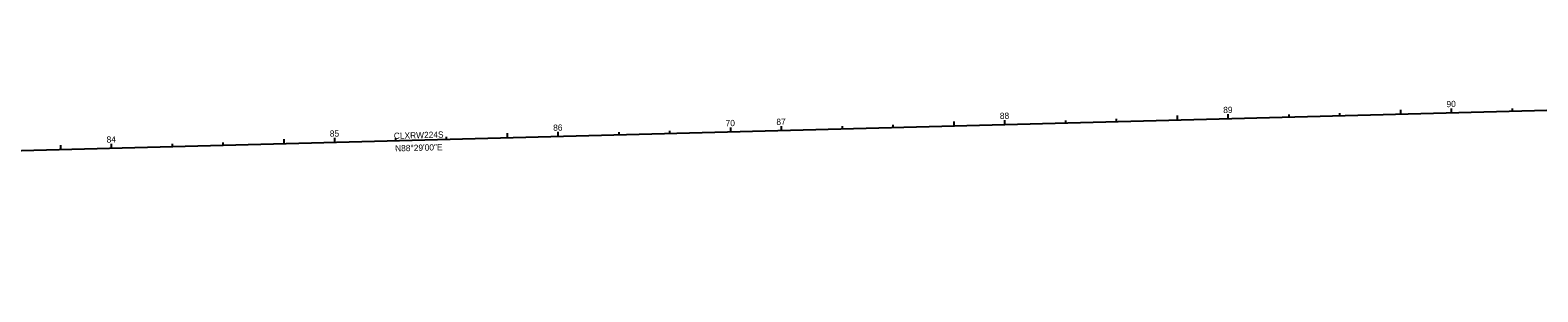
# Model space of a CAD drawing. Extents: x 2402033 to 2407434, y 498266 to 500417.
# Drawn here: x 2405397 to 2406072, y 498666 to 498783 of the extents above; entities that cross this region are included whole.
import ezdxf

# ---------------------------------------------------------------- set-up
doc = ezdxf.new("R2010")
doc.units = 0
for name, color, linetype in [('DR_P_Inlet_Protection', 7, 'Continuous'), ('DR_X_Cells', 7, 'Continuous'), ('DR_X_Elev_Flow', 7, 'Continuous'), ('PV_P_EOP', 7, 'Continuous'), ('PV_P_Shoulder', 7, 'Continuous'), ('RD_P_GR_Lt', 7, 'Continuous'), ('SN_X_Public', 7, 'Continuous'), ('UT_X_Gas_Cells', 7, 'Continuous'), ('UT_X_Telecom_Cells', 7, 'Continuous')]:
    doc.layers.add(name, color=color, linetype=linetype)

msp = doc.modelspace()

# ---------------------------------------------------------------- linework, layer by layer
at = {"layer": 'PV_P_EOP'}
msp.add_line((2403004.47, 498665.82), (2407431.7, 498783.04), dxfattribs=at)
at = {"layer": 'PV_P_Shoulder'}
for p, q in [((2405833.48, 498740.72), (2405833.45, 498741.92)), ((2405910.7, 498742.77), (2405910.67, 498743.96)), ((2405933.45, 498743.37), (2405933.41, 498744.57)), ((2406010.67, 498745.41), (2406010.64, 498746.61)), ((2406033.41, 498746.01), (2406033.36, 498748.01)), ((2405610.81, 498734.83), (2405610.78, 498736.02)), ((2405633.55, 498735.43), (2405633.52, 498736.63)), ((2405710.77, 498737.47), (2405710.72, 498739.47)), ((2405733.52, 498738.07), (2405733.49, 498739.27)), ((2405810.74, 498740.12), (2405810.71, 498741.32)), ((2405410.88, 498729.53), (2405410.85, 498730.73)), ((2405433.62, 498730.13), (2405433.59, 498731.33)), ((2405510.84, 498732.18), (2405510.81, 498733.38)), ((2405533.59, 498732.78), (2405533.53, 498734.78))]:
    msp.add_line(p, q, dxfattribs=at)
at = {"layer": 'RD_P_GR_Lt'}
for p, q in [((2405810.74, 498740.12), (2405810.68, 498742.12)), ((2405833.48, 498740.72), (2405833.43, 498742.72)), ((2405860.72, 498741.44), (2405860.69, 498742.64)), ((2405883.46, 498742.04), (2405883.43, 498743.24)), ((2405910.7, 498742.77), (2405910.65, 498744.76)), ((2405933.45, 498743.37), (2405933.39, 498745.37)), ((2405960.68, 498744.09), (2405960.65, 498745.29)), ((2405983.43, 498744.69), (2405983.4, 498745.89)), ((2406010.67, 498745.41), (2406010.61, 498747.41)), ((2406033.41, 498746.01), (2406033.36, 498748.01)), ((2406060.65, 498746.74), (2406060.62, 498747.93)), ((2405583.57, 498734.1), (2405583.54, 498735.3)), ((2405610.81, 498734.83), (2405610.75, 498736.82)), ((2405633.55, 498735.43), (2405633.5, 498737.43)), ((2405660.79, 498736.15), (2405660.76, 498737.35)), ((2405683.53, 498736.75), (2405683.5, 498737.95)), ((2405710.77, 498737.47), (2405710.72, 498739.47)), ((2405733.52, 498738.07), (2405733.46, 498740.07)), ((2405760.75, 498738.8), (2405760.72, 498739.99)), ((2405783.5, 498739.4), (2405783.47, 498740.6)), ((2405410.88, 498729.53), (2405410.82, 498731.53)), ((2405433.62, 498730.13), (2405433.57, 498732.13)), ((2405460.86, 498730.86), (2405460.83, 498732.05)), ((2405483.6, 498731.46), (2405483.57, 498732.66)), ((2405510.84, 498732.18), (2405510.79, 498734.18)), ((2405533.59, 498732.78), (2405533.53, 498734.78)), ((2405560.82, 498733.5), (2405560.79, 498734.7))]:
    msp.add_line(p, q, dxfattribs=at)
at = {"layer": 'SN_X_Public'}
for p, q in [((2406033.41, 498746.01), (2406033.36, 498748.01)), ((2405710.77, 498737.47), (2405710.72, 498739.47)), ((2405533.59, 498732.78), (2405533.56, 498733.98))]:
    msp.add_line(p, q, dxfattribs=at)

# ---------------------------------------------------------------- texts
at = {"layer": 'DR_P_Inlet_Protection'}
msp.add_text('N88°29\'00"E', height=2.8, rotation=1.5166, dxfattribs=at).set_placement((2405560.53, 498728.69))
at = {"layer": 'DR_X_Cells'}
msp.add_text('N88°29\'00"E', height=2.8, rotation=1.5166, dxfattribs=at).set_placement((2405560.53, 498728.69))
at = {"layer": 'DR_X_Elev_Flow'}
msp.add_text('CLXRW224S', height=2.8, rotation=1.5166, dxfattribs=at).set_placement((2405559.96, 498734.3))
at = {"layer": 'PV_P_Shoulder'}
for s, p in [('90', (2406031.15, 498748.5)), ('70', (2405708.48, 498739.95)), ('85', (2405531.31, 498735.27))]:
    msp.add_text(s, height=2.8, rotation=1.5166, dxfattribs=at).set_placement(p)
at = {"layer": 'RD_P_GR_Lt'}
for s, p in [('89', (2405931.22, 498745.86)), ('90', (2406031.15, 498748.5)), ('87', (2405731.2, 498740.56)), ('88', (2405831.22, 498743.21)), ('84', (2405431.4, 498732.62)), ('85', (2405531.31, 498735.27)), ('86', (2405631.29, 498737.92))]:
    msp.add_text(s, height=2.8, rotation=1.5166, dxfattribs=at).set_placement(p)
at = {"layer": 'SN_X_Public'}
for s, p in [('90', (2406031.15, 498748.5)), ('70', (2405708.48, 498739.95))]:
    msp.add_text(s, height=2.8, rotation=1.5166, dxfattribs=at).set_placement(p)
at = {"layer": 'UT_X_Gas_Cells'}
msp.add_text('CLXRW224S', height=2.8, rotation=1.5166, dxfattribs=at).set_placement((2405559.96, 498734.3))
at = {"layer": 'UT_X_Telecom_Cells'}
msp.add_text('CLXRW224S', height=2.8, rotation=1.5166, dxfattribs=at).set_placement((2405559.96, 498734.3))

doc.saveas('drawing.dxf')
